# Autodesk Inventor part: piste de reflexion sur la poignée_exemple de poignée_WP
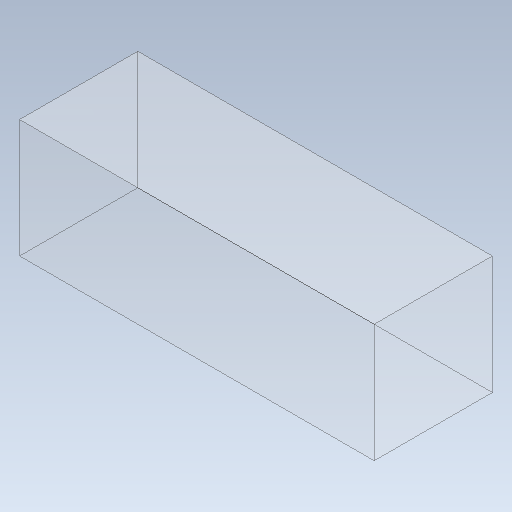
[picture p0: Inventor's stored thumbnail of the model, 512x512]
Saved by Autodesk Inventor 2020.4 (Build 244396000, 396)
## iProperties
Created: 2021-10
Part Number: piste de reflexion sur la poignée_exemple de poignée_WP
Material: Générique
Document SubType Name: Modeling
Designer: mel
Density: 1 g/cm^3
Appearance: Par défaut
Author: mel
d0: -50,000 mm
d1: 150,000 mm
d2: 150,000 mm
d3: 50,000 mm
d4: 50,000 mm
d5: 100,000 mm
d6: 0,00 deg
Xmin: -150,000 mm
Ymin: -50,000 mm
Zmin: -50,000 mm
Xmax: 150,000 mm
Ymax: 50,000 mm
Zmax: 50,000 mm
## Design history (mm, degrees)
sketch "Esquisse1"
  geometry: L1 (-150, 50)-(150, 50); L2 (150, 50)-(150, -50); L3 (150, -50)-(-150, -50); L4 (-150, -50)-(-150, 50); 1 further point
  constraints: 8 end point, 2 parallel, 1 horizontal, 1 perpendicular, 1 other
  dimensions: "d1" = 150 distance from line of L4 point (0, 0) (= -Xmin); "d2" = 150 distance from line of L2 point (0, 0) (= Xmax); "d3" = 50 distance from line of L3 point (0, 0) (= -Ymin); "d4" = 50 distance from line of L1 point (0, 0) (= Ymax)
extrude "Extrusion1" join sketch "Esquisse1" distance "d5" = 100 (= Zmax - Zmin); taper "d6" = 0 deg
node "Solide1"
other parameters: "Xmin" = -150 [user parameter; used in 1 equation term], "Ymin" = -50 [user parameter; used in 1 equation term], "Zmin" = -50 [user parameter; used in 1 equation term], "Xmax" = 150 [user parameter; used in 1 equation term], "Ymax" = 50 [user parameter; used in 1 equation term], "Zmax" = 50 [user parameter; used in 1 equation term], "d0" = -50
